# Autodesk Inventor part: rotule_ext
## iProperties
Author: robert
Shininess: 21.0
PropertySet Name: _Private Model Information
Compacted: True
Length Units: 11269
Angle Units: 11283
Time Units: 11279
Mass Units: 11290
Length Display Precision: 3
Angle Display Precision: 2
Created: 2001-08
Part Number: rotule_ext
Material: Par défaut
Document SubType Name: Modélisation
Designer: robert
Control State: 0
Master: False
Checked Out: False
PropertySet Name: Design Tracking Control
Density: 0.0
Volumn: 0.0
Area: 0.0
PropertySet Name: Model Information
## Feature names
1. Révolution1 [Revolution]
